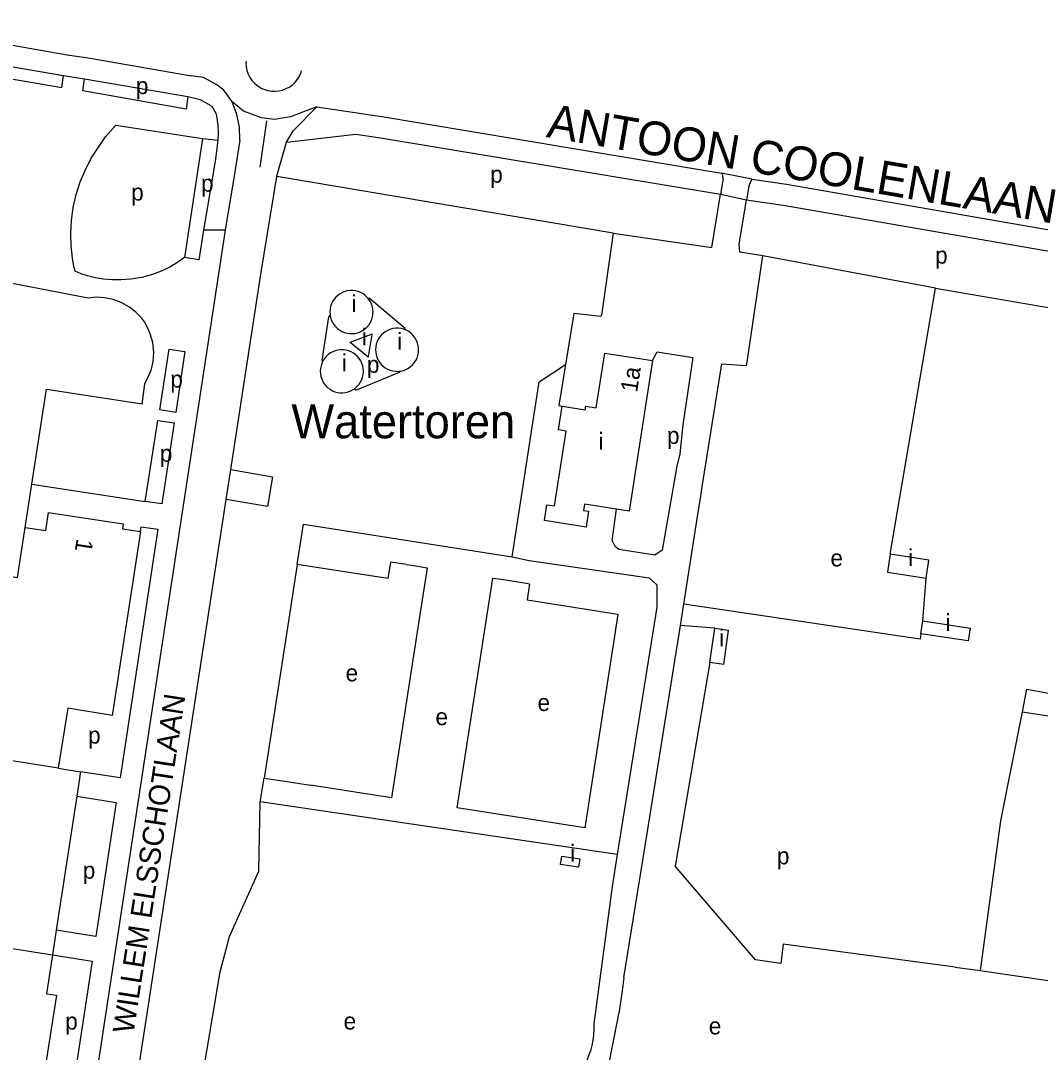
# Model space of a CAD drawing. Extents: x 161093 to 163177, y 379000 to 380904.
# Drawn here: x 161343.5 to 161584.6, y 380651.6 to 380895.5 of the extents above; entities that cross this region are included whole.
import ezdxf

# ---------------------------------------------------------------- set-up
doc = ezdxf.new("R2010")
doc.units = 0
for name, color, linetype in [('BLT_Basislijn', 7, 'Continuous'), ('BLT_Bebouwing', 7, 'Continuous'), ('BLT_Bebouwing_beschrifting', 7, 'Continuous'), ('BLT_Centroide', 7, 'Continuous'), ('BLT_Huisnummer', 7, 'Continuous'), ('BLT_Straatnaam', 7, 'Continuous'), ('BLT_Straatnaam_hoofdweg', 7, 'Continuous'), ('BLT_Vlakafsluiter', 7, 'Continuous')]:
    doc.layers.add(name, color=color, linetype=linetype)

msp = doc.modelspace()

# ---------------------------------------------------------------- linework, layer by layer
at = {"layer": 'BLT_Basislijn'}
for p, q in [((161308.24, 380895.51), (161354.49, 380887.45)), ((161307.39, 380890.58), (161353.63, 380882.52)), ((161354.49, 380887.45), (161359.42, 380886.7)), ((161359.42, 380886.7), (161383.87, 380882.49)), ((161353.63, 380882.52), (161358.57, 380881.78)), ((161358.57, 380881.78), (161383.02, 380877.56)), ((161400.13, 380860.83), (161401.68, 380871.85)), ((161386.48, 380867.64), (161382.25, 380839.5)), ((161483.57, 380845.23), (161404.07, 380858.65)), ((161516.47, 380858.03), (161509.25, 380859.47)), ((161509.43, 380857.24), (161508.95, 380854.45)), ((161515.62, 380855.91), (161515.1, 380853.18)), ((161508.95, 380854.45), (161515.1, 380853.18)), ((161391.8, 380845.99), (161360.68, 380641.96)), ((161391.8, 380845.99), (161386.73, 380845.99)), ((161559.79, 380832.24), (161519.01, 380839.89)), ((161549.1, 380769.36), (161559.79, 380832.24)), ((161559.79, 380832.24), (161593.47, 380826.51)), ((161416.68, 380825.71), (161416.24, 380825.51)), ((161393.15, 380789.37), (161397.81, 380819.69)), ((161392.06, 380782.28), (161393.15, 380789.37)), ((161344.54, 380775.72), (161346.14, 380785.95)), ((161504.22, 380782.54), (161504.59, 380784.86)), ((161503.79, 380779.79), (161504.22, 380782.54)), ((161500.28, 380757.57), (161503.79, 380779.79)), ((161457.08, 380763.44), (161462.64, 380762.57)), ((161556.82, 380753.59), (161557.61, 380763.74)), ((161499.49, 380752.55), (161500.28, 380757.57)), ((161491.61, 380703.38), (161499.49, 380752.55)), ((161507.61, 380751.91), (161499.49, 380752.55)), ((161506.44, 380743.73), (161498.23, 380695.66)), ((161581.37, 380737.43), (161586.64, 380736.52)), ((161352.34, 380718.78), (161357.65, 380717.95)), ((161357.65, 380717.95), (161356.75, 380712.16)), ((161400.14, 380710.8), (161401.02, 380716.45)), ((161424.05, 380712.87), (161412.02, 380714.74)), ((161356.75, 380712.16), (161351.83, 380680.5)), ((161431.16, 380711.76), (161424.05, 380712.87)), ((161484.57, 380698.37), (161400.14, 380710.8)), ((161486.15, 380669.32), (161491.61, 380703.38)), ((161484.57, 380698.37), (161483.37, 380690.82)), ((161483.37, 380690.82), (161479.03, 380658.36)), ((161351.83, 380680.5), (161351.02, 380674.65)), ((161564.49, 380671.78), (161570.35, 380670.93)), ((161486.15, 380669.32), (161485.7, 380666.14)), ((161485.7, 380666.14), (161484.95, 380660.79)), ((161484.68, 380659.42), (161484.95, 380660.79))]:
    msp.add_line(p, q, dxfattribs=at)
for points in [[(161307.39, 380890.58), (161307.22, 380887.56), (161353.2, 380879.67), (161353.63, 380882.52)], [(161396.76, 380885.95), (161396.73, 380885.54), (161396.8, 380884.61), (161396.99, 380883.71), (161397.29, 380882.86), (161397.69, 380882.08), (161398.17, 380881.38), (161398.72, 380880.77), (161399.3, 380880.26), (161399.9, 380879.83), (161400.52, 380879.49), (161401.21, 380879.2), (161401.96, 380878.98), (161402.78, 380878.85), (161403.64, 380878.81), (161404.52, 380878.89), (161405.41, 380879.1), (161406.28, 380879.43), (161407.1, 380879.87), (161407.84, 380880.43), (161408.5, 380881.07), (161409.05, 380881.78), (161409.48, 380882.53), (161409.81, 380883.3), (161409.92, 380883.66)], [(161393.48, 380876.3), (161392.42, 380877.92), (161391.48, 380879.03), (161389.9, 380880.33), (161386.68, 380882.06), (161383.87, 380882.49)], [(161383.02, 380877.56), (161382.58, 380874.61), (161358.14, 380878.92), (161358.57, 380881.78)], [(161383.02, 380877.56), (161385.91, 380876.83), (161388.66, 380875.25), (161389.67, 380873.44), (161390.08, 380870.91), (161390.17, 380869.01), (161390.07, 380867.21)], [(161395.33, 380867.21), (161395.23, 380870.32), (161394.62, 380873.31), (161393.48, 380876.3)], [(161406.37, 380866.81), (161407.94, 380869.45), (161413.48, 380875.11)], [(161413.48, 380875.11), (161429.32, 380872.73), (161509.25, 380859.47)], [(161382.25, 380839.5), (161380.44, 380838.25), (161378.71, 380837.26), (161376.67, 380836.26), (161374.66, 380835.51), (161372.15, 380834.82), (161369.54, 380834.38), (161367.12, 380834.22), (161365.07, 380834.25), (161363.08, 380834.4), (161361.14, 380834.73), (161359.31, 380835.18), (161357.81, 380835.66), (161356.32, 380836.25), (161356.08, 380837.42), (161355.7, 380839.39), (161355.54, 380840.84), (161355.39, 380842.3), (161355.34, 380845.09), (161355.47, 380848.28), (161355.9, 380851.35), (161356.6, 380854.44), (161357.53, 380857.39), (161358.71, 380860.1), (161360.17, 380863), (161361.84, 380865.58), (161363.53, 380868.02), (161365.94, 380870.77), (161386.48, 380867.64)], [(161386.48, 380867.64), (161390.07, 380867.21), (161389.54, 380862.73), (161386.73, 380845.99)], [(161406.37, 380866.81), (161422.73, 380868.67), (161428.54, 380867.8), (161508.95, 380854.45)], [(161395.33, 380867.21), (161394.19, 380860.23), (161391.8, 380845.99)], [(161404.07, 380858.65), (161404.14, 380859.09), (161406.37, 380866.81)], [(161397.81, 380819.69), (161400.32, 380836.05), (161404.07, 380858.65)], [(161509.25, 380859.47), (161509.33, 380859.28), (161509.46, 380858.74), (161509.52, 380858.18), (161509.5, 380857.62), (161509.43, 380857.24)], [(161516.47, 380858.03), (161516.24, 380857.7), (161515.96, 380857.18), (161515.76, 380856.63), (161515.63, 380856.05), (161515.62, 380855.91)], [(161516.47, 380858.03), (161524.57, 380856.84), (161622.55, 380839.85), (161673.98, 380831.54), (161678.16, 380830.1), (161681.32, 380827.9)], [(161483.57, 380845.23), (161506.95, 380841.87), (161508.95, 380854.45)], [(161519.01, 380839.89), (161513.54, 380840.75), (161513.42, 380842.65), (161515.1, 380853.18)], [(161515.1, 380853.18), (161523.78, 380851.9), (161595.88, 380839.4)], [(161386.73, 380845.99), (161385.62, 380838.98), (161382.25, 380839.5)], [(161346.14, 380785.95), (161349.58, 380808.42), (161372.17, 380804.95), (161372.86, 380809.68), (161373.72, 380811.46), (161374.38, 380813.15), (161374.79, 380814.92), (161374.93, 380817.1), (161374.71, 380819.39), (161374.12, 380821.46), (161373.5, 380822.94), (161372.72, 380824.28), (161372.01, 380825.23), (161370.74, 380826.58), (161369.24, 380827.77), (161367.27, 380828.87), (161365.36, 380829.6), (161363.33, 380829.99), (161361.36, 380830.11), (161359.42, 380829.89), (161329.53, 380835.64), (161324.48, 380842.84), (161303.23, 380845.01)], [(161483.57, 380845.23), (161480.85, 380825.86), (161480.7, 380825.6), (161474.27, 380826.27), (161472.32, 380814.23)], [(161504.59, 380784.86), (161509.28, 380814.39), (161515.05, 380813.99), (161515.21, 380814.31), (161519.01, 380839.89)], [(161434.37, 380822.43), (161434.41, 380822.75), (161425.92, 380829.93), (161425.65, 380829.81)], [(161416.24, 380825.51), (161414.68, 380815.18), (161414.91, 380814.98)], [(161382.32, 380817.28), (161380.13, 380802.89), (161376.37, 380803.46), (161378.6, 380817.85), (161382.32, 380817.28)], [(161492.93, 380815.15), (161493.99, 380817.18), (161502.42, 380815.89), (161500.1, 380799.92), (161499.38, 380793.11), (161498.63, 380790.15), (161495.19, 380770.33), (161493.44, 380769.18), (161484.93, 380770.47), (161484.1, 380771.16), (161483.35, 380772.59), (161484.37, 380779.98)], [(161459.72, 380768.72), (161466.1, 380810.11), (161472.32, 380814.23)], [(161472.32, 380814.23), (161470.75, 380804.54), (161471.51, 380804.33)], [(161422.39, 380808.48), (161422.75, 380808.16), (161433.05, 380812.44), (161433.08, 380812.64)], [(161372.93, 380781.84), (161375.9, 380800.99)], [(161375.9, 380800.99), (161379.75, 380800.4), (161376.83, 380781.25), (161372.93, 380781.84)], [(161393.15, 380789.37), (161403.06, 380787.69), (161401.86, 380780.62), (161392.06, 380782.28)], [(161346.14, 380785.95), (161372.93, 380781.84)], [(161351.72, 380521.12), (161360.32, 380575.65), (161392.06, 380782.28)], [(161375.92, 380775.25), (161366.97, 380716.49), (161357.65, 380717.95)], [(161371.78, 380774.77), (161371.94, 380775.86), (161375.92, 380775.25)], [(161408.87, 380766.97), (161410.39, 380776.46), (161459.72, 380768.72)], [(161434.73, 380766.92), (161430.94, 380767.51), (161430.34, 380763.63), (161408.87, 380766.97)], [(161459.72, 380768.72), (161463.71, 380767.91), (161492.07, 380763.79), (161493.92, 380762.14), (161493.88, 380756.84), (161484.57, 380698.37)], [(161408.87, 380766.97), (161406.24, 380750), (161401.02, 380716.45)], [(161434.73, 380766.92), (161435.88, 380766.74), (161439.62, 380766.16), (161437.11, 380750), (161431.16, 380711.76)], [(161462.64, 380762.57), (161463.81, 380762.39), (161463.22, 380758.55), (161484.72, 380755.21), (161483.91, 380750), (161476.86, 380704.71), (161446.68, 380709.4), (161452.99, 380750), (161455.13, 380763.74), (161457.08, 380763.44)], [(161556.36, 380750.54), (161556.18, 380749.31), (161500.28, 380757.57)], [(161581.37, 380737.43), (161580.31, 380732.14)], [(161580.32, 380732.14), (161575.18, 380706.3), (161570.35, 380670.93)], [(161580.32, 380732.14), (161647.24, 380721.96), (161648.12, 380721.58), (161666.5, 380718.53)], [(161401.02, 380716.45), (161405.96, 380715.68), (161412.02, 380714.74)], [(161356.75, 380712.16), (161366.09, 380710.69), (161361.26, 380679.01), (161351.83, 380680.5)], [(161381.41, 380615.77), (161390.63, 380670.67), (161392.83, 380679.02), (161399.83, 380694.41), (161400.14, 380710.8)], [(161564.49, 380671.78), (161523.82, 380677.2), (161523.22, 380672.65), (161517.28, 380673.44), (161498.23, 380695.66)], [(161351.02, 380674.65), (161360.37, 380673.18), (161353.52, 380628.16), (161352.04, 380628.38)], [(161570.35, 380670.93), (161603.63, 380666.07), (161597.24, 380623.99)], [(161479.03, 380658.36), (161479.02, 380657.07), (161478.93, 380655.78), (161478.77, 380654.5), (161478.52, 380653.23), (161478.2, 380651.98), (161477.79, 380650.75), (161477.32, 380649.55), (161476.77, 380648.38), (161476.15, 380647.25), (161475.46, 380646.16), (161474.7, 380645.11), (161474.26, 380644.56)], [(161481.56, 380645.59), (161482.42, 380647.85), (161484.68, 380659.42)]]:
    msp.add_lwpolyline(points, dxfattribs=at)
at = {"layer": 'BLT_Bebouwing'}
for p, q in [((161421.43, 380819.51), (161426.45, 380821.41)), ((161426.54, 380821.34), (161425.66, 380816.08)), ((161421.32, 380819.47), (161421.43, 380819.51)), ((161421.41, 380819.4), (161421.32, 380819.47)), ((161425.55, 380816.05), (161421.41, 380819.4)), ((161470.64, 380798.74), (161471.51, 380804.33)), ((161371.78, 380774.77), (161365.13, 380731.27)), ((161549.1, 380769.36), (161548.46, 380765.15)), ((161548.46, 380765.15), (161557.61, 380763.74)), ((161556.36, 380750.54), (161556.82, 380753.59)), ((161506.44, 380743.73), (161507.61, 380751.91)), ((161507.61, 380751.91), (161510.9, 380751.44)), ((161509.73, 380743.26), (161506.44, 380743.73)), ((161354.61, 380732.99), (161352.34, 380718.78)), ((161365.13, 380731.27), (161354.61, 380732.99)), ((161352.34, 380718.78), (161325.55, 380722.99)), ((161318.78, 380679.71), (161351.02, 380674.65)), ((161351.02, 380674.65), (161349.55, 380665.47)), ((161351.94, 380665.09), (161346.3, 380629.28))]:
    msp.add_line(p, q, dxfattribs=at)
for points in [[(161425.65, 380829.81), (161425.42, 380830.09), (161424.96, 380830.53), (161424.44, 380830.9), (161423.88, 380831.21), (161423.29, 380831.45), (161422.67, 380831.61), (161422.04, 380831.7), (161421.4, 380831.7), (161420.77, 380831.62), (161420.15, 380831.47), (161419.55, 380831.24), (161418.99, 380830.93), (161418.47, 380830.56), (161418, 380830.13), (161417.59, 380829.64), (161417.25, 380829.1), (161416.97, 380828.53), (161416.77, 380827.92), (161416.64, 380827.3), (161416.6, 380826.66), (161416.63, 380826.02), (161416.68, 380825.71)], [(161426.8, 380826.61), (161426.76, 380827.24), (161426.64, 380827.87), (161426.44, 380828.48), (161426.17, 380829.06), (161425.83, 380829.6), (161425.65, 380829.81)], [(161416.68, 380825.71), (161416.74, 380825.39), (161416.93, 380824.78), (161417.2, 380824.2), (161417.53, 380823.66), (161417.93, 380823.16), (161418.39, 380822.72), (161418.91, 380822.34), (161419.46, 380822.02), (161420.05, 380821.78), (161420.67, 380821.61), (161421.3, 380821.52), (161421.94, 380821.51), (161422.57, 380821.58), (161423.19, 380821.73), (161423.79, 380821.96), (161424.36, 380822.26), (161424.88, 380822.62), (161425.35, 380823.05), (161425.77, 380823.54), (161426.12, 380824.07), (161426.4, 380824.64), (161426.61, 380825.24), (161426.74, 380825.87), (161426.79, 380826.51), (161426.8, 380826.61)], [(161426.45, 380821.41), (161426.56, 380821.45), (161426.54, 380821.34)], [(161434.37, 380822.43), (161434.09, 380822.54), (161433.47, 380822.7), (161432.84, 380822.79), (161432.2, 380822.79), (161431.56, 380822.71), (161430.94, 380822.56), (161430.35, 380822.33), (161429.79, 380822.02), (161429.27, 380821.65), (161428.8, 380821.22), (161428.39, 380820.73), (161428.04, 380820.19), (161427.77, 380819.62), (161427.56, 380819.01), (161427.44, 380818.39), (161427.39, 380817.75), (161427.43, 380817.11), (161427.54, 380816.48), (161427.73, 380815.87), (161427.99, 380815.29), (161428.33, 380814.75), (161428.73, 380814.25), (161429.19, 380813.81), (161429.7, 380813.43), (161430.26, 380813.11), (161430.85, 380812.87), (161431.46, 380812.7), (161432.1, 380812.61), (161432.73, 380812.6), (161433.08, 380812.64)], [(161437.59, 380817.7), (161437.55, 380818.33), (161437.43, 380818.96), (161437.24, 380819.57), (161436.96, 380820.15), (161436.62, 380820.69), (161436.22, 380821.18), (161435.75, 380821.62), (161435.24, 380821.99), (161434.68, 380822.3), (161434.37, 380822.43)], [(161424.52, 380812.62), (161424.48, 380813.25), (161424.37, 380813.88), (161424.17, 380814.49), (161423.9, 380815.07), (161423.56, 380815.61), (161423.15, 380816.1), (161422.69, 380816.54), (161422.17, 380816.91), (161421.61, 380817.22), (161421.02, 380817.46), (161420.4, 380817.62), (161419.77, 380817.71), (161419.13, 380817.71), (161418.5, 380817.63), (161417.88, 380817.48), (161417.28, 380817.24), (161416.72, 380816.94), (161416.2, 380816.57), (161415.73, 380816.14), (161415.32, 380815.65), (161414.98, 380815.11), (161414.91, 380814.98)], [(161433.08, 380812.64), (161433.37, 380812.67), (161433.99, 380812.82), (161434.59, 380813.05), (161435.15, 380813.35), (161435.67, 380813.71), (161436.15, 380814.14), (161436.56, 380814.63), (161436.91, 380815.16), (161437.2, 380815.73), (161437.41, 380816.33), (161437.54, 380816.96), (161437.59, 380817.6), (161437.59, 380817.7)], [(161471.51, 380804.33), (161477, 380803.48), (161477.13, 380804.33), (161479.58, 380803.95), (161481.6, 380816.92), (161492.93, 380815.15)], [(161414.91, 380814.98), (161414.7, 380814.54), (161414.5, 380813.93), (161414.37, 380813.3), (161414.32, 380812.67), (161414.36, 380812.03), (161414.47, 380811.4), (161414.66, 380810.79), (161414.93, 380810.21), (161415.26, 380809.67), (161415.66, 380809.17), (161416.12, 380808.73), (161416.64, 380808.35), (161417.19, 380808.03), (161417.78, 380807.79), (161418.4, 380807.62), (161419.03, 380807.53), (161419.67, 380807.52), (161420.3, 380807.59), (161420.92, 380807.74), (161421.52, 380807.97), (161422.08, 380808.27), (161422.39, 380808.48)], [(161425.66, 380816.08), (161425.64, 380815.97), (161425.55, 380816.05)], [(161492.93, 380815.15), (161487.38, 380779.52), (161484.37, 380779.98)], [(161422.39, 380808.48), (161422.61, 380808.63), (161423.08, 380809.06), (161423.5, 380809.55), (161423.85, 380810.08), (161424.13, 380810.65), (161424.34, 380811.25), (161424.47, 380811.88), (161424.52, 380812.52), (161424.52, 380812.62)], [(161467.34, 380777.34), (161467.92, 380781.07), (161469.7, 380780.8), (161472.45, 380798.45), (161470.64, 380798.74)], [(161484.37, 380779.98), (161476.81, 380781.16), (161476.59, 380779.72), (161477.75, 380779.54), (161477.17, 380775.8), (161467.34, 380777.34)], [(161344.54, 380775.72), (161349.39, 380774.96), (161350.05, 380779.21), (161367.7, 380776.51), (161367.53, 380775.4), (161371.78, 380774.77)], [(161262.04, 380576.82), (161266.7, 380607.19), (161238.48, 380612.29), (161248.7, 380668.91), (161251.34, 380668.43), (161254.72, 380687.17), (161261.86, 380685.88), (161264.78, 380702.03), (161258.81, 380702.96), (161265.16, 380743.79), (161286.19, 380740.52), (161291.52, 380772.43), (161342.69, 380763.87), (161344.54, 380775.72)], [(161558.21, 380767.94), (161549.1, 380769.36)], [(161557.61, 380763.74), (161558.21, 380767.94)], [(161556.82, 380753.59), (161568, 380751.91), (161567.54, 380748.86), (161556.36, 380750.54)], [(161509.73, 380743.26), (161510.9, 380751.44)], [(161471.17, 380696.05), (161471.47, 380697.99), (161475.71, 380697.33), (161475.41, 380695.39), (161471.17, 380696.05)], [(161349.55, 380665.47), (161351.94, 380665.09)]]:
    msp.add_lwpolyline(points, dxfattribs=at)
at = {"layer": 'BLT_Vlakafsluiter'}
msp.add_lwpolyline([(161413.48, 380875.11), (161410.34, 380873.92), (161407.25, 380872.73), (161403.52, 380872.15), (161400.42, 380872.49), (161396.19, 380874.08), (161393.48, 380876.3)], dxfattribs=at)

# ---------------------------------------------------------------- texts
at = {"layer": 'BLT_Bebouwing_beschrifting'}
msp.add_text('Watertoren', height=8, dxfattribs=at).set_placement((161407.5, 380796.78))
at = {"layer": 'BLT_Centroide'}
for s, p in [('p', (161370.72, 380878.13)), ('p', (161454.51, 380857.18)), ('p', (161386.12, 380855.07)), ('p', (161369.59, 380852.96)), ('p', (161559.72, 380838.06)), ('i', (161421.7, 380826.59)), ('i', (161424.17, 380818.72)), ('i', (161432.49, 380817.69)), ('i', (161419.43, 380812.62)), ('p', (161425.35, 380812.24)), ('p', (161378.86, 380808.75)), ('i', (161480.12, 380794.09)), ('p', (161496.32, 380795.44)), ('p', (161376.37, 380791.2)), ('i', (161553.34, 380766.56)), ('e', (161534.98, 380766.48)), ('i', (161562.18, 380751.22)), ('i', (161508.67, 380747.58)), ('e', (161420.31, 380739.31)), ('e', (161465.7, 380732.3)), ('e', (161441.56, 380728.94)), ('p', (161359.4, 380724.59)), ('i', (161473.44, 380696.69)), ('p', (161522.32, 380696.05)), ('p', (161358.15, 380692.65)), ('p', (161354, 380656.98)), ('e', (161419.84, 380657)), ('e', (161506.2, 380655.85))]:
    msp.add_text(s, height=4, dxfattribs=at).set_placement(p)
at = {"layer": 'BLT_Huisnummer'}
for s, rotation, p in [('1a', 81.279, (161489.24, 380807.48)), ('1', 261.1356, (161356.73, 380773.17))]:
    msp.add_text(s, height=4, rotation=rotation, dxfattribs=at).set_placement(p)
at = {"layer": 'BLT_Straatnaam'}
msp.add_text('WILLEM ELSSCHOTLAAN', height=5, rotation=81.2662, dxfattribs=at).set_placement((161370.15, 380655.87))
at = {"layer": 'BLT_Straatnaam_hoofdweg'}
msp.add_text('ANTOON COOLENLAAN', height=8, rotation=350.3187, dxfattribs=at).set_placement((161467.59, 380868.01))

doc.saveas('drawing.dxf')
